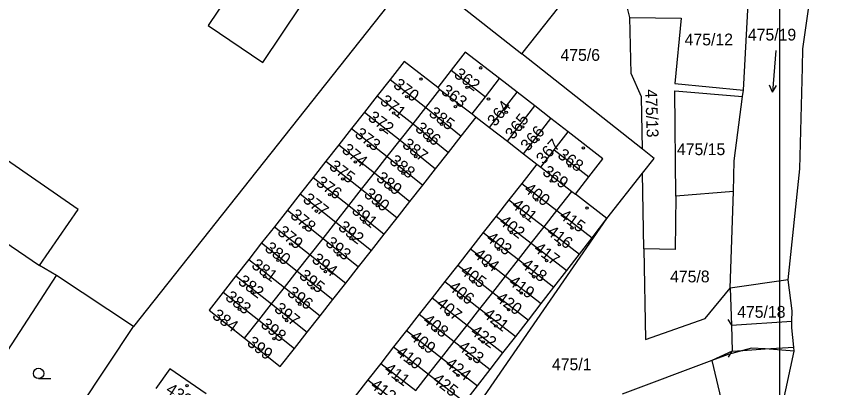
# Model space of a CAD drawing. Extents: x -558500 to -557517, y -1073973 to -1073051.
# Drawn here: x -557909.9 to -557793.1, y -1073343.1 to -1073289.5 of the extents above; entities that cross this region are included whole.
import ezdxf

# ---------------------------------------------------------------- set-up
doc = ezdxf.new("R2010")
doc.units = 0
for name, color, linetype in [('Default', 7, 'Continuous'), ('Hranice parcel', 7, 'Continuous'), ('Parcelní čísla', 7, 'Continuous'), ('Vnitřní kresba', 7, 'Continuous'), ('Značky budov', 7, 'Continuous'), ('Značky kultur', 7, 'Continuous')]:
    doc.layers.add(name, color=color, linetype=linetype)

msp = doc.modelspace()

# ---------------------------------------------------------------- linework, layer by layer
at = {"layer": 'Default'}
msp.add_lwpolyline([(-557909.21, -1073700), (-558500, -1073700), (-558500, -1073200), (-557800, -1073200), (-557800, -1073567.6)], dxfattribs=at)
at = {"layer": 'Hranice parcel'}
for p, q in [((-557796.66, -1073294.23), (-557793.06, -1073269.04)), ((-557837.1, -1073294.96), (-557823.76, -1073277.98)), ((-557852.38, -1073282.88), (-557892.99, -1073334.25)), ((-557852.38, -1073282.88), (-557837.1, -1073294.96)), ((-557821.55, -1073289.72), (-557823.08, -1073283.72)), ((-557805.19, -1073300.2), (-557804.5, -1073287.75)), ((-557819.71, -1073308.7), (-557837.1, -1073294.96)), ((-557847.28, -1073297.31), (-557849.22, -1073299.81)), ((-557847.28, -1073297.31), (-557842.35, -1073301.13)), ((-557842.35, -1073301.13), (-557840.32, -1073298.51)), ((-557837.79, -1073300.48), (-557840.32, -1073298.51)), ((-557856.07, -1073298.63), (-557857.92, -1073300.99)), ((-557856.07, -1073298.63), (-557850.92, -1073302.67)), ((-557815.1, -1073299.21), (-557805.19, -1073300.2)), ((-557850.92, -1073302.67), (-557848.89, -1073300.07)), ((-557849.22, -1073299.81), (-557848.89, -1073300.07)), ((-557848.89, -1073300.07), (-557844.27, -1073303.61)), ((-557841.74, -1073305.57), (-557837.79, -1073300.48)), ((-557835.23, -1073302.46), (-557837.79, -1073300.48)), ((-557805.35, -1073301.09), (-557805.19, -1073300.2)), ((-557857.92, -1073300.99), (-557859.76, -1073303.34)), ((-557857.92, -1073300.99), (-557852.77, -1073305.03)), ((-557844.27, -1073303.61), (-557842.35, -1073301.13)), ((-557852.77, -1073305.03), (-557850.92, -1073302.67)), ((-557850.92, -1073302.67), (-557845.82, -1073306.79)), ((-557839.19, -1073307.55), (-557835.23, -1073302.46)), ((-557832.93, -1073304.25), (-557835.23, -1073302.46)), ((-557859.76, -1073303.34), (-557861.61, -1073305.7)), ((-557859.76, -1073303.34), (-557854.62, -1073307.38)), ((-557845.82, -1073306.79), (-557843.68, -1073304.07)), ((-557844.27, -1073303.61), (-557843.68, -1073304.07)), ((-557843.68, -1073304.07), (-557841.74, -1073305.57)), ((-557836.88, -1073309.34), (-557832.93, -1073304.25)), ((-557830.43, -1073306.19), (-557832.93, -1073304.25)), ((-557854.62, -1073307.38), (-557852.77, -1073305.03)), ((-557852.77, -1073305.03), (-557847.66, -1073309.15)), ((-557861.61, -1073305.7), (-557863.46, -1073308.06)), ((-557861.61, -1073305.7), (-557856.47, -1073309.74)), ((-557841.74, -1073305.57), (-557839.19, -1073307.55)), ((-557832.44, -1073308.79), (-557830.43, -1073306.19)), ((-557856.47, -1073309.74), (-557854.62, -1073307.38)), ((-557854.62, -1073307.38), (-557849.51, -1073311.5)), ((-557847.66, -1073309.15), (-557845.82, -1073306.79)), ((-557839.19, -1073307.55), (-557836.88, -1073309.34)), ((-557863.46, -1073308.06), (-557865.31, -1073310.42)), ((-557863.46, -1073308.06), (-557858.32, -1073312.1)), ((-557834.38, -1073311.28), (-557832.44, -1073308.79)), ((-557832.44, -1073308.79), (-557827.44, -1073312.66)), ((-557858.32, -1073312.1), (-557856.47, -1073309.74)), ((-557856.47, -1073309.74), (-557851.36, -1073313.85)), ((-557849.51, -1073311.5), (-557847.66, -1073309.15)), ((-557836.88, -1073309.34), (-557834.95, -1073310.84)), ((-557865.31, -1073310.42), (-557867.16, -1073312.77)), ((-557865.31, -1073310.42), (-557860.17, -1073314.46)), ((-557834.95, -1073310.84), (-557837.12, -1073313.61)), ((-557834.95, -1073310.84), (-557834.38, -1073311.28)), ((-557834.38, -1073311.28), (-557829.9, -1073314.76)), ((-557860.17, -1073314.46), (-557858.32, -1073312.1)), ((-557858.32, -1073312.1), (-557853.21, -1073316.21)), ((-557851.36, -1073313.85), (-557849.51, -1073311.5)), ((-557819.52, -1073323.02), (-557819.71, -1073312.13)), ((-557867.16, -1073312.77), (-557869.01, -1073315.13)), ((-557867.16, -1073312.77), (-557862.02, -1073316.82)), ((-557837.12, -1073313.61), (-557838.96, -1073315.96)), ((-557837.12, -1073313.61), (-557832.06, -1073317.52)), ((-557829.38, -1073315.16), (-557827.44, -1073312.66)), ((-557923.1, -1073314.09), (-557906.54, -1073325.46)), ((-557862.02, -1073316.82), (-557860.17, -1073314.46)), ((-557860.17, -1073314.46), (-557855.06, -1073318.56)), ((-557853.21, -1073316.21), (-557851.36, -1073313.85)), ((-557832.06, -1073317.52), (-557829.9, -1073314.76)), ((-557829.9, -1073314.76), (-557829.38, -1073315.16)), ((-557806.64, -1073314.76), (-557814.95, -1073315.46)), ((-557807.11, -1073328.71), (-557806.64, -1073314.76)), ((-557869.01, -1073315.13), (-557870.86, -1073317.49)), ((-557869.01, -1073315.13), (-557863.87, -1073319.18)), ((-557838.96, -1073315.96), (-557840.81, -1073318.32)), ((-557838.96, -1073315.96), (-557833.9, -1073319.88)), ((-557863.87, -1073319.18), (-557862.02, -1073316.82)), ((-557862.02, -1073316.82), (-557856.91, -1073320.91)), ((-557855.06, -1073318.56), (-557853.21, -1073316.21)), ((-557870.86, -1073317.49), (-557872.71, -1073319.85)), ((-557870.86, -1073317.49), (-557865.72, -1073321.53)), ((-557840.81, -1073318.32), (-557842.65, -1073320.68)), ((-557840.81, -1073318.32), (-557835.75, -1073322.24)), ((-557833.9, -1073319.88), (-557832.06, -1073317.52)), ((-557832.06, -1073317.52), (-557826.99, -1073321.44)), ((-557865.72, -1073321.53), (-557863.87, -1073319.18)), ((-557863.87, -1073319.18), (-557858.76, -1073323.27)), ((-557856.91, -1073320.91), (-557855.06, -1073318.56)), ((-557872.71, -1073319.85), (-557874.56, -1073322.2)), ((-557872.71, -1073319.85), (-557867.58, -1073323.89)), ((-557842.65, -1073320.68), (-557844.5, -1073323.04)), ((-557842.65, -1073320.68), (-557837.6, -1073324.6)), ((-557835.75, -1073322.24), (-557833.9, -1073319.88)), ((-557833.9, -1073319.88), (-557828.82, -1073323.81)), ((-557867.58, -1073323.89), (-557865.72, -1073321.53)), ((-557865.72, -1073321.53), (-557860.61, -1073325.62)), ((-557858.76, -1073323.27), (-557856.91, -1073320.91)), ((-557828.82, -1073323.81), (-557826.99, -1073321.44)), ((-557874.56, -1073322.2), (-557876.41, -1073324.56)), ((-557874.56, -1073322.2), (-557869.43, -1073326.25)), ((-557844.5, -1073323.04), (-557846.34, -1073325.39)), ((-557844.5, -1073323.04), (-557839.45, -1073326.96)), ((-557837.6, -1073324.6), (-557835.75, -1073322.24)), ((-557835.75, -1073322.24), (-557830.65, -1073326.18)), ((-557869.43, -1073326.25), (-557867.58, -1073323.89)), ((-557867.58, -1073323.89), (-557862.46, -1073327.97)), ((-557860.61, -1073325.62), (-557858.76, -1073323.27)), ((-557830.65, -1073326.18), (-557828.82, -1073323.81)), ((-557876.41, -1073324.56), (-557878.26, -1073326.92)), ((-557876.41, -1073324.56), (-557871.28, -1073328.61)), ((-557839.45, -1073326.96), (-557837.6, -1073324.6)), ((-557837.6, -1073324.6), (-557832.49, -1073328.56)), ((-557904.1, -1073326.9), (-557906.54, -1073325.46)), ((-557871.28, -1073328.61), (-557869.43, -1073326.25)), ((-557869.43, -1073326.25), (-557864.3, -1073330.32)), ((-557862.46, -1073327.97), (-557860.61, -1073325.62)), ((-557846.34, -1073325.39), (-557848.19, -1073327.75)), ((-557846.34, -1073325.39), (-557841.29, -1073329.31)), ((-557832.49, -1073328.56), (-557830.65, -1073326.18)), ((-557911.75, -1073338.65), (-557904.1, -1073326.9)), ((-557892.99, -1073334.25), (-557904.1, -1073326.9)), ((-557878.26, -1073326.92), (-557880.11, -1073329.28)), ((-557878.26, -1073326.92), (-557873.13, -1073330.97)), ((-557841.29, -1073329.31), (-557839.45, -1073326.96)), ((-557839.45, -1073326.96), (-557834.32, -1073330.93)), ((-557798.75, -1073327.52), (-557807.11, -1073328.71)), ((-557873.13, -1073330.97), (-557871.28, -1073328.61)), ((-557871.28, -1073328.61), (-557866.15, -1073332.68)), ((-557864.3, -1073330.32), (-557862.46, -1073327.97)), ((-557848.19, -1073327.75), (-557850.03, -1073330.11)), ((-557848.19, -1073327.75), (-557843.14, -1073331.67)), ((-557834.32, -1073330.93), (-557832.49, -1073328.56)), ((-557807.11, -1073328.71), (-557806.93, -1073334.05)), ((-557880.11, -1073329.28), (-557874.98, -1073333.33)), ((-557843.14, -1073331.67), (-557841.29, -1073329.31)), ((-557841.29, -1073329.31), (-557836.16, -1073333.3)), ((-557874.98, -1073333.33), (-557873.13, -1073330.97)), ((-557873.13, -1073330.97), (-557868, -1073335.03)), ((-557866.15, -1073332.68), (-557864.3, -1073330.32)), ((-557850.03, -1073330.11), (-557851.88, -1073332.47)), ((-557850.03, -1073330.11), (-557844.98, -1073334.03)), ((-557836.16, -1073333.3), (-557834.32, -1073330.93)), ((-557844.98, -1073334.03), (-557843.14, -1073331.67)), ((-557843.14, -1073331.67), (-557837.99, -1073335.67)), ((-557877.01, -1073335.92), (-557874.98, -1073333.33)), ((-557874.98, -1073333.33), (-557869.85, -1073337.38)), ((-557868, -1073335.03), (-557866.15, -1073332.68)), ((-557851.88, -1073332.47), (-557853.72, -1073334.82)), ((-557851.88, -1073332.47), (-557846.83, -1073336.4)), ((-557837.99, -1073335.67), (-557836.16, -1073333.3)), ((-557911.2, -1073361.51), (-557892.99, -1073334.25)), ((-557846.83, -1073336.4), (-557844.98, -1073334.03)), ((-557844.98, -1073334.03), (-557839.83, -1073338.04)), ((-557806.93, -1073334.05), (-557806.8, -1073337.79)), ((-557869.85, -1073337.38), (-557868, -1073335.03)), ((-557853.72, -1073334.82), (-557855.57, -1073337.18)), ((-557853.72, -1073334.82), (-557848.67, -1073338.75)), ((-557839.83, -1073338.04), (-557837.99, -1073335.67)), ((-557848.67, -1073338.75), (-557846.83, -1073336.4)), ((-557846.83, -1073336.4), (-557841.66, -1073340.41)), ((-557855.57, -1073337.18), (-557857.41, -1073339.54)), ((-557855.57, -1073337.18), (-557850.52, -1073341.11)), ((-557841.66, -1073340.41), (-557839.83, -1073338.04)), ((-557806.8, -1073337.79), (-557809.74, -1073339.14)), ((-557809.37, -1073390.13), (-557797.89, -1073337.76)), ((-557850.52, -1073341.11), (-557848.67, -1073338.75)), ((-557848.67, -1073338.75), (-557843.49, -1073342.78)), ((-557809.74, -1073339.14), (-557822.65, -1073343.99)), ((-557857.41, -1073339.54), (-557859.26, -1073341.9)), ((-557857.41, -1073339.54), (-557852.37, -1073343.47)), ((-557843.49, -1073342.78), (-557841.66, -1073340.41)), ((-557852.37, -1073343.47), (-557850.52, -1073341.11)), ((-557850.52, -1073341.11), (-557845.33, -1073345.15)), ((-557859.26, -1073341.9), (-557861.1, -1073344.25)), ((-557859.26, -1073341.9), (-557854.22, -1073345.83)), ((-557845.33, -1073345.15), (-557843.49, -1073342.78))]:
    msp.add_line(p, q, dxfattribs=at)
for points in [[(-557863.55, -1073279.98), (-557871.4, -1073274.72), (-557882.24, -1073290.87), (-557874.41, -1073296.22), (-557863.55, -1073279.98)], [(-557819.71, -1073308.7), (-557819.88, -1073301.16), (-557821.38, -1073297.78), (-557821.55, -1073289.72)], [(-557821.55, -1073289.72), (-557814.17, -1073289.81), (-557815.1, -1073299.21)], [(-557840.32, -1073298.51), (-557845.25, -1073294.69), (-557847.28, -1073297.31)], [(-557798.75, -1073327.52), (-557797.09, -1073311.5), (-557796.72, -1073296.93), (-557796.66, -1073294.23)], [(-557849.22, -1073299.81), (-557854.03, -1073296.04), (-557856.07, -1073298.63)], [(-557814.95, -1073315.46), (-557815.09, -1073300.29), (-557805.35, -1073301.09)], [(-557806.64, -1073314.76), (-557806.53, -1073310.37), (-557805.35, -1073301.09)], [(-557906.54, -1073325.46), (-557900.99, -1073317.38), (-557917.44, -1073306)], [(-557827.44, -1073312.66), (-557825.43, -1073310.07), (-557830.43, -1073306.19)], [(-557819.71, -1073312.13), (-557818.05, -1073310.01), (-557819.71, -1073308.7)], [(-557856.89, -1073365.11), (-557824.85, -1073318.68), (-557819.71, -1073312.13)], [(-557826.99, -1073321.44), (-557824.85, -1073318.68), (-557829.38, -1073315.16)], [(-557814.95, -1073315.46), (-557815.04, -1073323.14), (-557819.52, -1073323.02)], [(-557819.52, -1073323.02), (-557819.31, -1073336.08), (-557810.73, -1073333.1), (-557807.11, -1073328.71)], [(-557797.89, -1073337.76), (-557797.95, -1073337.19), (-557798.25, -1073334.44), (-557798.23, -1073333.47), (-557798.2, -1073331.98), (-557798.75, -1073327.52)], [(-557880.11, -1073329.28), (-557882.14, -1073331.87), (-557877.01, -1073335.92)], [(-557877.01, -1073335.92), (-557871.88, -1073339.97), (-557869.85, -1073337.38)], [(-557797.89, -1073337.76), (-557802.06, -1073337.47), (-557804.02, -1073337.33), (-557805.31, -1073337.69), (-557807.41, -1073338.27), (-557809.74, -1073339.14)], [(-557809.74, -1073339.14), (-557808.21, -1073345.61), (-557807.79, -1073349.5), (-557808.41, -1073352.55)], [(-557882.54, -1073343.92), (-557887.8, -1073340.34), (-557889.79, -1073343.18)]]:
    msp.add_lwpolyline(points, dxfattribs=at)
at = {"layer": 'Vnitřní kresba'}
for p, q in [((-557807.47, -1073333.21), (-557806.93, -1073334.05)), ((-557806.93, -1073334.05), (-557798.23, -1073333.47)), ((-557807.34, -1073338.63), (-557806.8, -1073337.79)), ((-557806.8, -1073337.79), (-557805.31, -1073337.69)), ((-557805.31, -1073337.69), (-557802.06, -1073337.47)), ((-557802.06, -1073337.47), (-557797.95, -1073337.19))]:
    msp.add_line(p, q, dxfattribs=at)
at = {"layer": 'Značky budov'}
for centre in [(-557843.03, -1073296.97), (-557851.63, -1073298.58), (-557844.99, -1073299.77), (-557853.67, -1073301.13), (-557841.9, -1073301.47), (-557846.66, -1073302.56), (-557855.54, -1073303.48), (-557839.36, -1073303.38), (-557848.65, -1073305.08), (-557837.01, -1073305.48), (-557857.37, -1073305.86), (-557850.54, -1073307.47), (-557834.77, -1073307.3), (-557859.21, -1073308.18), (-557828.24, -1073308.51), (-557852.37, -1073309.77), (-557861.07, -1073310.53), (-557830.21, -1073311.11), (-557854.22, -1073312.14), (-557862.91, -1073312.98), (-557832.87, -1073313.25), (-557856.08, -1073314.44), (-557864.77, -1073315.23), (-557834.96, -1073316.02), (-557857.91, -1073316.83), (-557827.72, -1073317.16), (-557866.67, -1073317.61), (-557836.78, -1073318.36), (-557859.79, -1073319.2), (-557868.48, -1073319.96), (-557838.61, -1073320.72), (-557829.88, -1073320.03), (-557861.68, -1073321.59), (-557870.37, -1073322.34), (-557840.43, -1073323.11), (-557831.72, -1073322.42), (-557863.53, -1073323.92), (-557872.21, -1073324.69), (-557842.3, -1073325.44), (-557833.54, -1073324.73), (-557865.39, -1073326.31), (-557874.11, -1073327.04), (-557844.09, -1073327.8), (-557835.38, -1073327.07), (-557867.24, -1073328.67), (-557875.91, -1073329.36), (-557845.87, -1073330.1), (-557837.17, -1073329.41), (-557869.07, -1073331.01), (-557877.77, -1073331.73), (-557847.74, -1073332.5), (-557839.01, -1073331.8), (-557870.96, -1073333.4), (-557849.54, -1073334.84), (-557840.85, -1073334.14), (-557872.8, -1073335.99), (-557842.67, -1073336.45), (-557851.37, -1073337.26), (-557853.19, -1073339.56), (-557844.51, -1073338.87), (-557846.3, -1073341.26), (-557885.3, -1073342.76), (-557855.07, -1073341.99)]:
    msp.add_circle(centre, 0.175, dxfattribs=at)
at = {"layer": 'Značky kultur'}
for p, q in [((-557800.52, -1073294.48), (-557801.04, -1073300.46)), ((-557801.04, -1073300.46), (-557801.46, -1073299.44)), ((-557801.04, -1073300.46), (-557800.46, -1073299.52)), ((-557906.67, -1073341.73), (-557904.92, -1073341.73))]:
    msp.add_line(p, q, dxfattribs=at)
msp.add_circle((-557906.67, -1073340.98), 0.75, dxfattribs=at)

# ---------------------------------------------------------------- texts
at = {"layer": 'Parcelní čísla'}
for s, p in [('475/19', (-557804.56, -1073293.03)), ('475/12', (-557813.66, -1073293.73)), ('475/6', (-557831.54, -1073295.96)), ('475/15', (-557814.77, -1073309.54)), ('475/8', (-557815.76, -1073327.87)), ('475/18', (-557806.1, -1073332.97)), ('475/1', (-557832.77, -1073340.53))]:
    msp.add_text(s, height=1.7, dxfattribs=at).set_placement(p)
for s, rotation, p in [('362', 324, (-557846.99, -1073298.19)), ('370', 323, (-557855.74, -1073299.67)), ('363', 324, (-557848.85, -1073300.58)), ('475/13', 272, (-557819.35, -1073300.08)), ('371', 322, (-557857.63, -1073302.02)), ('364', 52, (-557840.91, -1073305.51)), ('385', 323, (-557850.62, -1073303.77)), ('372', 324, (-557859.39, -1073304.4)), ('365', 52, (-557838.34, -1073307.39)), ('386', 321, (-557852.58, -1073305.92)), ('366', 49, (-557836.2, -1073309.09)), ('373', 323, (-557861.28, -1073306.77)), ('387', 322, (-557854.45, -1073308.27)), ('367', 48, (-557833.98, -1073310.98)), ('374', 321, (-557863.14, -1073309)), ('368', 324, (-557832.08, -1073309.81)), ('388', 321, (-557856.28, -1073310.62)), ('375', 323, (-557864.97, -1073311.43)), ('369', 324, (-557834.27, -1073312.24)), ('389', 322, (-557858.19, -1073313.09)), ('376', 324, (-557866.87, -1073313.78)), ('390', 321, (-557859.96, -1073315.4)), ('400', 323, (-557836.9, -1073314.71)), ('377', 322, (-557868.75, -1073316.16)), ('391', 321, (-557861.71, -1073317.76)), ('401', 321, (-557838.71, -1073316.96)), ('378', 321, (-557870.57, -1073318.43)), ('415', 324, (-557831.82, -1073318.54)), ('392', 322, (-557863.67, -1073320.16)), ('402', 322, (-557840.49, -1073319.35)), ('379', 321, (-557872.42, -1073320.84)), ('416', 323, (-557833.63, -1073320.86)), ('393', 321, (-557865.5, -1073322.42)), ('403', 322, (-557842.36, -1073321.74)), ('380', 323, (-557874.24, -1073323.22)), ('417', 323, (-557835.5, -1073323.27)), ('394', 322, (-557867.47, -1073324.82)), ('404', 322, (-557844.18, -1073324.12)), ('381', 324, (-557876.15, -1073325.67)), ('418', 322, (-557837.31, -1073325.59)), ('395', 321, (-557869.29, -1073327.14)), ('405', 323, (-557846.05, -1073326.52)), ('382', 323, (-557878.09, -1073327.99)), ('419', 324, (-557839.13, -1073328.09)), ('396', 323, (-557871.01, -1073329.63)), ('406', 321, (-557847.76, -1073328.8)), ('383', 322, (-557879.92, -1073330.25)), ('420', 324, (-557840.95, -1073330.45)), ('397', 321, (-557872.88, -1073331.91)), ('407', 321, (-557849.55, -1073331.16)), ('384', 325, (-557881.8, -1073332.94)), ('421', 322, (-557842.8, -1073332.73)), ('398', 321, (-557874.83, -1073334.16)), ('408', 322, (-557851.48, -1073333.59)), ('422', 324, (-557844.61, -1073335.23)), ('399', 322, (-557876.79, -1073336.81)), ('409', 322, (-557853.33, -1073335.97)), ('423', 323, (-557846.4, -1073337.46)), ('410', 323, (-557855.33, -1073338.24)), ('424', 323, (-557848.24, -1073339.88)), ('411', 323, (-557857.07, -1073340.65)), ('425', 322, (-557850.11, -1073342.12)), ('430', 327, (-557888.49, -1073343.66)), ('412', 323, (-557859.02, -1073342.96))]:
    msp.add_text(s, height=1.7, rotation=rotation, dxfattribs=at).set_placement(p)

doc.saveas('drawing.dxf')
